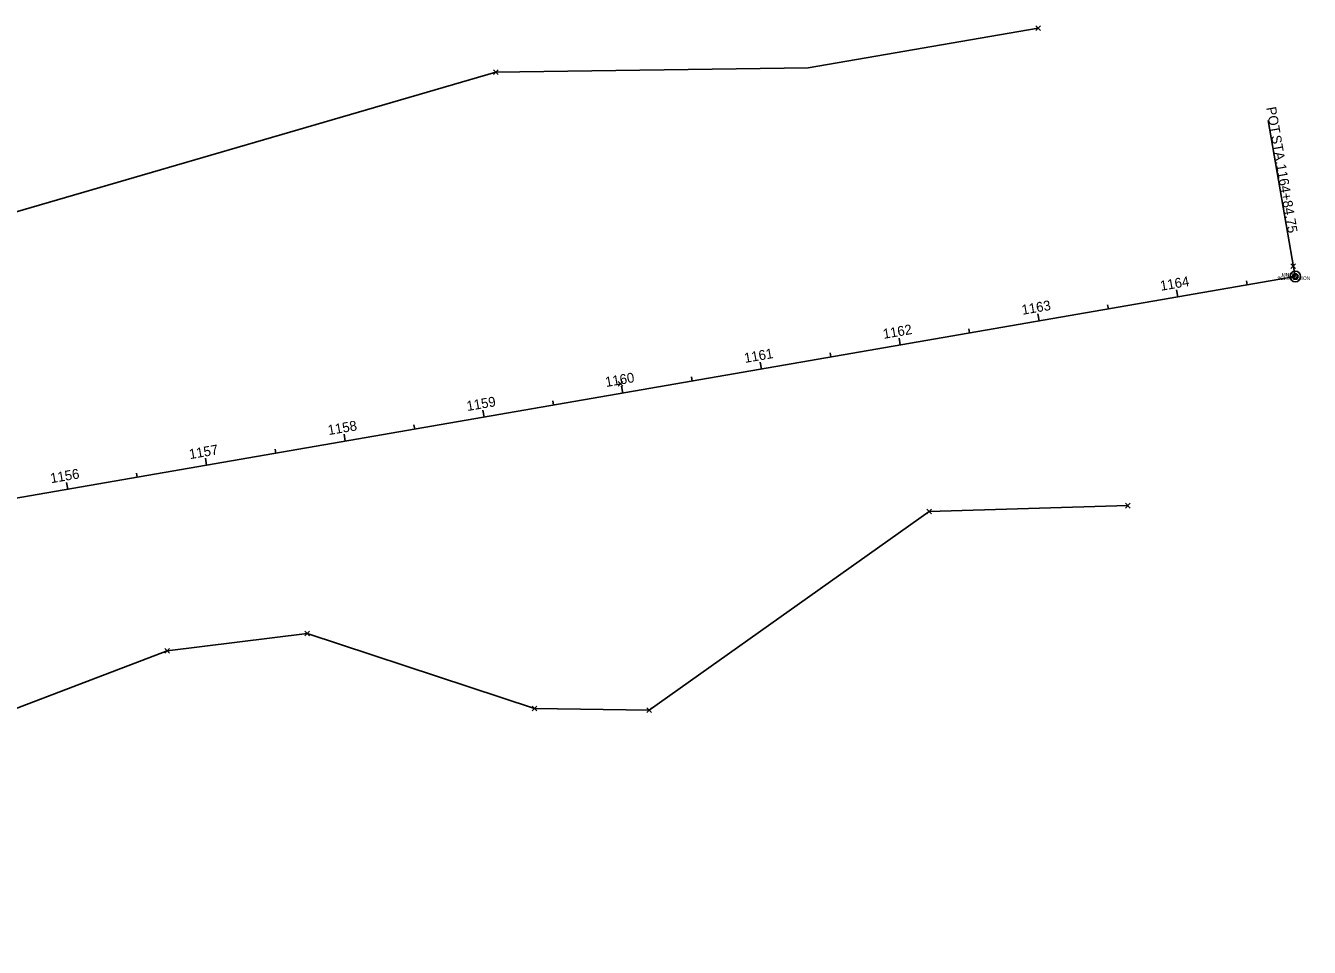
# Model space of a CAD drawing. Extents: x 2082101 to 2090447, y 708207 to 709766.
# Drawn here: x 2087148 to 2088060, y 708552 to 709207 of the extents above; entities that cross this region are included whole.
import ezdxf

# ---------------------------------------------------------------- set-up
doc = ezdxf.new("R2010")
doc.units = 0
for name, color, linetype in [('DR_X_Ditch', 7, 'Continuous'), ('DR_X_Elev_Flow', 7, 'Continuous'), ('GK_Drainage_Nodes', 7, 'Continuous'), ('SV_X_Break_Lines', 7, 'Continuous'), ('SV_X_Mon_Cells_Found', 7, 'Continuous'), ('SV_X_Shot_Marker', 7, 'Continuous'), ('SV_X_Text_Comment', 7, 'Continuous'), ('SV_X_Text_Elevation', 7, 'Continuous'), ('SV_X_Text_Name', 7, 'Continuous'), ('SV_X_Toe_of_Slope', 7, 'Continuous')]:
    doc.layers.add(name, color=color, linetype=linetype)

msp = doc.modelspace()

# ---------------------------------------------------------------- linework, layer by layer
at = {"layer": 'DR_X_Ditch'}
for p, q in [((2087703.58, 709176.78), (2087867.04, 709205.11)), ((2087481.72, 709173.84), (2087703.58, 709176.78)), ((2086708.85, 708948.54), (2087481.72, 709173.84)), ((2087789.53, 708861.83), (2087930.59, 708865.98)), ((2087590.7, 708720.8), (2087789.53, 708861.83)), ((2087248.47, 708762.97), (2087347.85, 708775.12)), ((2087347.85, 708775.12), (2087509.31, 708721.91)), ((2086915.31, 708635.7), (2087248.47, 708762.97)), ((2087509.31, 708721.91), (2087590.7, 708720.8))]:
    msp.add_line(p, q, dxfattribs=at)
at = {"layer": 'DR_X_Elev_Flow'}
msp.add_line((2088049.6, 709028.7), (2088030.39, 709139.54), dxfattribs=at)
msp.add_circle((2088049.6, 709028.7), 1.5, dxfattribs=at)
at = {"layer": 'GK_Drainage_Nodes'}
for p, q in [((2088015.36, 709022.76), (2088014.85, 709025.72)), ((2087966.1, 709014.22), (2087965.24, 709019.15)), ((2087916.83, 709005.68), (2087916.32, 709008.64)), ((2087867.57, 708997.14), (2087866.71, 709002.07)), ((2087769.04, 708980.07), (2087768.18, 708984.99)), ((2087818.3, 708988.6), (2087817.79, 708991.56)), ((2087670.51, 708962.99), (2087669.65, 708967.91)), ((2087719.77, 708971.53), (2087719.26, 708974.48)), ((2087621.24, 708954.45), (2087620.73, 708957.4)), ((2087571.97, 708945.91), (2087571.12, 708950.83)), ((2087522.71, 708937.37), (2087522.2, 708940.32)), ((2087473.44, 708928.83), (2087472.59, 708933.76)), ((2087424.18, 708920.29), (2087423.67, 708923.25)), ((2087374.91, 708911.75), (2087374.06, 708916.68)), ((2087325.65, 708903.21), (2087325.14, 708906.17)), ((2087276.38, 708894.67), (2087275.53, 708899.6)), ((2087227.12, 708886.13), (2087226.6, 708889.09)), ((2087177.85, 708877.59), (2087177, 708882.52))]:
    msp.add_line(p, q, dxfattribs=at)
at = {"layer": 'SV_X_Break_Lines'}
for p, q in [((2087865.38, 709203.44), (2087868.71, 709206.78)), ((2087865.38, 709206.78), (2087868.71, 709203.44)), ((2087480.05, 709172.17), (2087483.39, 709175.51)), ((2087480.05, 709175.51), (2087483.39, 709172.17)), ((2087928.93, 708864.31), (2087932.26, 708867.65)), ((2087928.93, 708867.65), (2087932.26, 708864.31)), ((2087787.86, 708860.16), (2087791.2, 708863.5)), ((2087787.86, 708863.5), (2087791.2, 708860.16)), ((2087346.18, 708773.45), (2087349.52, 708776.79)), ((2087346.18, 708776.79), (2087349.52, 708773.45)), ((2087246.8, 708761.3), (2087250.13, 708764.64)), ((2087246.8, 708764.64), (2087250.13, 708761.3)), ((2087507.64, 708720.25), (2087510.98, 708723.58)), ((2087507.64, 708723.58), (2087510.98, 708720.25)), ((2087589.03, 708719.13), (2087592.36, 708722.47)), ((2087589.03, 708722.47), (2087592.36, 708719.13))]:
    msp.add_line(p, q, dxfattribs=at)
at = {"layer": 'SV_X_Shot_Marker'}
msp.add_line((2085301.62, 708552.38), (2088049.6, 709028.7), dxfattribs=at)
at = {"layer": 'SV_X_Text_Name'}
for p, q in [((2088046.35, 709034.38), (2088049.68, 709037.71)), ((2088046.35, 709037.71), (2088049.68, 709034.38)), ((2087568.58, 708950.9), (2087571.92, 708954.24)), ((2087568.58, 708954.24), (2087571.92, 708950.9))]:
    msp.add_line(p, q, dxfattribs=at)
at = {"layer": 'SV_X_Toe_of_Slope'}
for radius in [3.75, 2]:
    msp.add_circle((2088049.6, 709028.7), radius, dxfattribs=at)

# ---------------------------------------------------------------- texts
at = {"layer": 'DR_X_Elev_Flow'}
for s, p in [('POT', (2088028.91, 709148.57)), (' STA. ', (2088031.96, 709131.01)), ('1164+84.75', (2088035.94, 709108.04))]:
    msp.add_text(s, height=7, rotation=279.83357, dxfattribs=at).set_placement(p)
at = {"layer": 'GK_Drainage_Nodes'}
for s, p in [('1164', (2087954.2, 709018.5)), ('1163', (2087855.87, 709001.46)), ('1162', (2087757.31, 708984.38)), ('1161', (2087658.75, 708967.29)), ('1160', (2087560.11, 708950.19)), ('1159', (2087461.68, 708933.13)), ('1158', (2087363.09, 708916.04)), ('1157', (2087264.57, 708898.97)), ('1156', (2087166.01, 708881.88))]:
    msp.add_text(s, height=7, rotation=9.83357, dxfattribs=at).set_placement(p)
at = {"layer": 'SV_X_Mon_Cells_Found'}
msp.add_text('CMON', height=2.5, dxfattribs=at).set_placement((2088049.6, 709026.2))
at = {"layer": 'SV_X_Text_Comment'}
msp.add_text('861.885', height=2.5, dxfattribs=at).set_placement((2088036.92, 709026.2))
at = {"layer": 'SV_X_Text_Elevation'}
msp.add_text('MN20', height=2.5, dxfattribs=at).set_placement((2088039.92, 709028.7))

doc.saveas('drawing.dxf')
